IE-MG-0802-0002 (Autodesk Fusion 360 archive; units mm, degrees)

design "IS-MG-0802-0001" references "LED", "Ethernet Port", "SFP SLOT", "Digitus_DN-651107_LAN-Switch", "POWER"
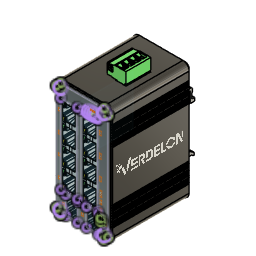
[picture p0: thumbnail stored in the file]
sketch "Sketch2" plane through (0, 0, 0) normal (0, 1, 0) x axis (1, 0, 0)
  line L1 (40, 0) -> (5, 0)
  line L2 (45, -90) -> (45, -5)
  line L3 (5, -95) -> (40, -95)
  line L4 (0, -5) -> (0, -90)
  arc A1 centre (5, -90) radius 5 clockwise from (5, -95) to (0, -90)
  arc A2 centre (40, -90) radius 5 clockwise from (45, -90) to (40, -95)
  arc A3 centre (40, -5) radius 5 clockwise from (40, 0) to (45, -5)
  arc A4 centre (5, -5) radius 5 clockwise from (0, -5) to (5, 0)
  point P1 (0, 0)
  point P2 (0, 0)
  point P4 (0, -95)
  point P3 (45, 0)
  horizontal L1
  vertical L2
  horizontal L3
  vertical L4
  coincident P1 P2
  coincident P4 L3
  coincident P4 L4
  tangent L3 A1
  tangent L4 A1
  tangent L2 A2
  tangent L3 A2
  equal A1 A2
  coincident P3 L1
  coincident P3 L2
  tangent L1 A3
  tangent L2 A3
  equal A1 A3
  coincident P2 L1
  coincident P2 L4
  tangent L1 A4
  tangent L4 A4
  dimension "d1" distance P2 P4 = 95
  dimension "d2" distance P2 P3 = 45
  dimension "d3" radius A1 = 5
  dimension "d6" radius A4 = 5
extrude "Extrude1" new body sketch "Sketch2" against normal blind 65
sketch "Sketch8" plane through (0, 0, 0) normal (0, 1, 0) x axis (-1, 0, 0)
  line L1 (-5, 0) -> (-40, 0)
  line L2 (0, 90) -> (0, 5)
  line L3 (-40, 95) -> (-5, 95)
  line L4 (-45, 5) -> (-45, 90)
  line L5 (-5, 1.5) -> (-40, 1.5)
  line L6 (-40, 0) -> (-5, 0)
  line L7 (-5, 95) -> (-40, 95)
  line L8 (0, 5) -> (0, 90)
  line L9 (-45, 5) -> (-45, 90)
  line L10 (-40, 1.5) -> (-5, 1.5)
  line L11 (-43.5, 5) -> (-43.5, 90)
  line L12 (-5, 93.5) -> (-40, 93.5)
  line L13 (-1.5, 5) -> (-1.5, 90)
  line L14 (0, 5) -> (0, 90)
  arc A1 centre (-40, 5) radius 5 clockwise from (-40, 0) to (-45, 5)
  arc A2 centre (-5, 5) radius 5 clockwise from (0, 5) to (-5, 0)
  arc A3 centre (-5, 90) radius 5 clockwise from (-5, 95) to (0, 90)
  arc A4 centre (-40, 90) radius 5 clockwise from (-45, 90) to (-40, 95)
  arc A5 centre (-40, 90) radius 4.6022 clockwise from (-43.6478, 87.194) to (-44.1163, 87.9418)
  arc A6 centre (-40, 5) radius 3.5 clockwise from (-40, 1.5) to (-43.5, 5)
  arc A7 centre (-5, 5) radius 3.5 clockwise from (-1.5, 5) to (-5, 1.5)
  arc A8 centre (-40, 90) radius 5 clockwise from (-45, 90) to (-40, 95)
  arc A9 centre (-5, 90) radius 5 clockwise from (-5, 95) to (0, 90)
  arc A10 centre (-5, 5) radius 5 clockwise from (0, 5) to (-5, 0)
  arc A11 centre (-40, 5) radius 5 clockwise from (-40, 0) to (-45, 5)
  arc A12 centre (-40, 5) radius 3.5 clockwise from (-40, 1.5) to (-43.5, 5)
  arc A13 centre (-40, 90) radius 3.5 clockwise from (-43.5, 90) to (-40, 93.5)
  arc A14 centre (-5, 90) radius 3.5 clockwise from (-5, 93.5) to (-1.5, 90)
  arc A15 centre (-5, 5) radius 3.5 clockwise from (-1.5, 5) to (-5, 1.5)
  horizontal L6
  horizontal L7
  vertical L8
  tangent L7 A8
  tangent L7 A9
  tangent L8 A9
  tangent L6 A10
  tangent L8 A10
  tangent L6 A11
  concentric A4 A5
  concentric A1 A6
  concentric A2 A7
  tangent A6 L5
  tangent L5 A7
  tangent A11 L9
  dimension "d14" radius A8 = 5
  dimension "d15" radius A9 = 5
  dimension "d16" radius A10 = 5
  dimension "d17" radius A11 = 5
  dimension "d168" = -1.5
  dimension "d169" distance L8 = 0
extrude "Extrude2" cut sketch "Sketch8" profile of A1 L1 A2 L2 A3 L3 A4 L4 L5 A6 A7 L6 L7 L8 A9 A10 L13 A12 L10 L12 L11 A15 A13 A14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 against normal blind 1.5
sketch "Sketch15" plane through (0, -65, 0) normal (0, -1, 0) x axis (1, 0, 0)
  line L1 (45, 90) -> (45, 5)
  line L2 (5, 95) -> (40, 95)
  line L3 (0, 5) -> (0, 90)
  line L4 (40, 0) -> (5, 0)
  line L5 (40, 1.5) -> (5, 1.5)
  line L6 (43.5, 90) -> (43.5, 5)
  line L7 (5, 93.5) -> (40, 93.5)
  line L8 (1.5, 5) -> (1.5, 90)
  line L9 (0, 5) -> (0, 90)
  line L10 (40, 0) -> (5, 0)
  line L11 (45, 90) -> (45, 5)
  line L12 (5, 95) -> (40, 95)
  arc A1 centre (40, 5) radius 5 clockwise from (45, 5) to (40, 0)
  arc A2 centre (40, 90) radius 5 clockwise from (40, 95) to (45, 90)
  arc A3 centre (5, 90) radius 5 clockwise from (0, 90) to (5, 95)
  arc A4 centre (5, 5) radius 5 clockwise from (5, 0) to (0, 5)
  arc A5 centre (40, 5) radius 3.5 clockwise from (43.5, 5) to (40, 1.5)
  arc A6 centre (40, 90) radius 3.5 clockwise from (40, 93.5) to (43.5, 90)
  arc A7 centre (5, 90) radius 3.5 clockwise from (1.5, 90) to (5, 93.5)
  arc A8 centre (5, 5) radius 3.5 clockwise from (5, 1.5) to (1.5, 5)
  arc A9 centre (5, 5) radius 5 clockwise from (5, 0) to (0, 5)
  arc A10 centre (40, 5) radius 5 clockwise from (45, 5) to (40, 0)
  arc A11 centre (40, 90) radius 5 clockwise from (40, 95) to (45, 90)
  arc A12 centre (5, 90) radius 5 clockwise from (0, 90) to (5, 95)
  dimension "d170" = -1.5
  dimension "d171" distance L3 = 0
  dimension "d172" = 0
extrude "Extrude3" cut sketch "Sketch15" against normal blind 1.5
sketch "Sketch17" plane through (0, -63.5, 0) normal (0, -1, 0) x axis (1, 0, 0)
  line L1 (40, 0) -> (5, 0)
  line L2 (45, 90) -> (45, 5)
  line L3 (5, 95) -> (40, 95)
  line L4 (0, 5) -> (0, 90)
  line L5 (-18.3053, 47.5) -> (0, 47.5)
  line L6 (0.5, 68.5) -> (0, 68.5)
  line L7 (0.5, 67.5) -> (0.5, 68.5)
  line L8 (0, 67.5) -> (0.5, 67.5)
  line L9 (0, 68.5) -> (0, 67.5)
  line L10 (0.5, 69.25) -> (0.5, 70.25)
  line L11 (0, 69.25) -> (0.5, 69.25)
  line L12 (0, 70.25) -> (0, 69.25)
  line L13 (0.5, 70.25) -> (0, 70.25)
  line L14 (0.5, 71) -> (0.5, 72)
  line L15 (0, 71) -> (0.5, 71)
  line L16 (0, 72) -> (0, 71)
  line L17 (0.5, 72) -> (0, 72)
  line L18 (0, 76) -> (0, 75)
  line L19 (0.5, 75) -> (0.5, 76)
  line L20 (0, 77.75) -> (0, 76.75)
  line L21 (0, 73.25) -> (0.5, 73.25)
  line L22 (0, 76.75) -> (0.5, 76.75)
  line L23 (0.5, 73.25) -> (0.5, 74.25)
  line L24 (0.5, 76) -> (0, 76)
  line L25 (0.5, 76.75) -> (0.5, 77.75)
  line L26 (0.5, 74.25) -> (0, 74.25)
  line L27 (0.5, 77.75) -> (0, 77.75)
  line L28 (0, 74.25) -> (0, 73.25)
  line L29 (0, 75) -> (0.5, 75)
  line L30 (0, 81.75) -> (0, 80.75)
  line L31 (0.5, 80.75) -> (0.5, 81.75)
  line L32 (0, 83.5) -> (0, 82.5)
  line L33 (0, 79) -> (0.5, 79)
  line L34 (0, 82.5) -> (0.5, 82.5)
  line L35 (0.5, 79) -> (0.5, 80)
  line L36 (0.5, 81.75) -> (0, 81.75)
  line L37 (0.5, 82.5) -> (0.5, 83.5)
  line L38 (0.5, 80) -> (0, 80)
  line L39 (0.5, 83.5) -> (0, 83.5)
  line L40 (0, 80) -> (0, 79)
  line L41 (0, 80.75) -> (0.5, 80.75)
  line L42 (0.5, 17.25) -> (0, 17.25)
  line L43 (0, 20.75) -> (0, 21.75)
  line L44 (0.5, 20) -> (0.5, 19)
  line L45 (0, 23) -> (0, 24)
  line L46 (0, 19) -> (0, 20)
  line L47 (0, 15) -> (0, 16)
  line L48 (0.5, 13.25) -> (0, 13.25)
  line L49 (0, 17.25) -> (0, 18.25)
  line L50 (0.5, 27.5) -> (0.5, 26.5)
  line L51 (0, 13.25) -> (0, 14.25)
  line L52 (0.5, 21.75) -> (0.5, 20.75)
  line L53 (0.5, 18.25) -> (0.5, 17.25)
  line L54 (0, 27.5) -> (0.5, 27.5)
  line L55 (0, 16) -> (0.5, 16)
  line L56 (0.5, 14.25) -> (0.5, 13.25)
  line L57 (0.5, 20.75) -> (0, 20.75)
  line L58 (0.5, 24.75) -> (0, 24.75)
  line L59 (0.5, 11.5) -> (0, 11.5)
  line L60 (0.5, 19) -> (0, 19)
  line L61 (0, 24) -> (0.5, 24)
  line L62 (0, 25.75) -> (0.5, 25.75)
  line L63 (0.5, 16) -> (0.5, 15)
  line L64 (0, 11.5) -> (0, 12.5)
  line L65 (0, 14.25) -> (0.5, 14.25)
  line L66 (0, 20) -> (0.5, 20)
  line L67 (0.5, 26.5) -> (0, 26.5)
  line L68 (0.5, 12.5) -> (0.5, 11.5)
  line L69 (0, 24.75) -> (0, 25.75)
  line L70 (0.5, 25.75) -> (0.5, 24.75)
  line L71 (0, 12.5) -> (0.5, 12.5)
  line L72 (0, 18.25) -> (0.5, 18.25)
  line L73 (0.5, 15) -> (0, 15)
  line L74 (0.5, 23) -> (0, 23)
  line L75 (0, 21.75) -> (0.5, 21.75)
  line L76 (0.5, 24) -> (0.5, 23)
  line L77 (0, 26.5) -> (0, 27.5)
  line L78 (22.5, 100) -> (22.5, 95)
  line L79 (45, 82.5) -> (44.5, 82.5)
  line L80 (45, 77.75) -> (45, 76.75)
  line L81 (44.5, 80) -> (45, 80)
  line L82 (45, 76.75) -> (44.5, 76.75)
  line L83 (45, 68.5) -> (45, 67.5)
  line L84 (45, 75) -> (44.5, 75)
  line L85 (44.5, 76) -> (45, 76)
  line L86 (44.5, 82.5) -> (44.5, 83.5)
  line L87 (45, 74.25) -> (45, 73.25)
  line L88 (44.5, 80.75) -> (44.5, 81.75)
  line L89 (44.5, 68.5) -> (45, 68.5)
  line L90 (45, 67.5) -> (44.5, 67.5)
  line L91 (45, 79) -> (44.5, 79)
  line L92 (45, 70.25) -> (45, 69.25)
  line L93 (44.5, 75) -> (44.5, 76)
  line L94 (45, 73.25) -> (44.5, 73.25)
  line L95 (44.5, 72) -> (45, 72)
  line L96 (45, 80) -> (45, 79)
  line L97 (44.5, 67.5) -> (44.5, 68.5)
  line L98 (44.5, 74.25) -> (45, 74.25)
  line L99 (44.5, 70.25) -> (45, 70.25)
  line L100 (45, 76) -> (45, 75)
  line L101 (44.5, 77.75) -> (45, 77.75)
  line L102 (45, 69.25) -> (44.5, 69.25)
  line L103 (44.5, 71) -> (44.5, 72)
  line L104 (44.5, 69.25) -> (44.5, 70.25)
  line L105 (44.5, 83.5) -> (45, 83.5)
  line L106 (45, 81.75) -> (45, 80.75)
  line L107 (44.5, 79) -> (44.5, 80)
  line L108 (44.5, 73.25) -> (44.5, 74.25)
  line L109 (44.5, 81.75) -> (45, 81.75)
  line L110 (45, 80.75) -> (44.5, 80.75)
  line L111 (45, 71) -> (44.5, 71)
  line L112 (44.5, 76.75) -> (44.5, 77.75)
  line L113 (45, 83.5) -> (45, 82.5)
  line L114 (45, 72) -> (45, 71)
  line L115 (44.5, 21.75) -> (44.5, 20.75)
  line L116 (44.5, 14.25) -> (44.5, 13.25)
  line L117 (45, 21.75) -> (44.5, 21.75)
  line L118 (44.5, 11.5) -> (45, 11.5)
  line L119 (45, 11.5) -> (45, 12.5)
  line L120 (44.5, 13.25) -> (45, 13.25)
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  point P15 (0, 47.5)
  point P17 (0, 68.5)
  point P78 (0, 26.5)
  point P18 (0.5, 68.5)
  point P88 (0.5, 26.5)
  point P19 (0.5, 67.5)
  point P60 (0.5, 27.5)
  point P20 (0, 67.5)
  point P81 (0, 27.5)
  point P21 (0.5, 70.25)
  point P87 (0.5, 24.75)
  point P22 (0.5, 69.25)
  point P82 (0.5, 25.75)
  point P23 (0, 69.25)
  point P79 (0, 25.75)
  point P24 (0, 70.25)
  point P85 (0, 24.75)
  point P25 (0.5, 72)
  point P71 (0.5, 23)
  point P26 (0.5, 71)
  point P67 (0.5, 24)
  point P27 (0, 71)
  point P69 (0, 24)
  point P28 (0, 72)
  point P65 (0, 23)
  point P29 (0, 75)
  point P63 (0, 20)
  point P30 (0, 76)
  point P56 (0, 19)
  point P31 (0.5, 74.25)
  point P55 (0.5, 20.75)
  point P32 (0, 73.25)
  point P59 (0, 21.75)
  point P33 (0.5, 73.25)
  point P54 (0.5, 21.75)
  point P34 (0, 74.25)
  point P53 (0, 20.75)
  point P35 (0.5, 76)
  point P58 (0.5, 19)
  point P36 (0.5, 75)
  point P57 (0.5, 20)
  point P37 (0, 76.75)
  point P62 (0, 18.25)
  point P38 (0, 77.75)
  point P75 (0, 17.25)
  point P39 (0.5, 77.75)
  point P73 (0.5, 17.25)
  point P40 (0.5, 76.75)
  point P84 (0.5, 18.25)
  point P41 (0, 80.75)
  point P70 (0, 14.25)
  point P42 (0, 81.75)
  point P64 (0, 13.25)
  point P43 (0.5, 80)
  point P61 (0.5, 15)
  point P44 (0, 79)
  point P66 (0, 16)
  point P45 (0.5, 79)
  point P76 (0.5, 16)
  point P46 (0, 80)
  point P68 (0, 15)
  point P47 (0.5, 81.75)
  point P72 (0.5, 13.25)
  point P48 (0.5, 80.75)
  point P74 (0.5, 14.25)
  point P49 (0, 82.5)
  point P77 (0, 12.5)
  point P50 (0, 83.5)
  point P80 (0, 11.5)
  point P51 (0.5, 83.5)
  point P83 (0.5, 11.5)
  point P52 (0.5, 82.5)
  point P86 (0.5, 12.5)
  point P89 (22.5, 95)
  point P2 (5, 5)
  point P155 (40, 5)
  point P3 (5, 90)
  point P113 (40, 90)
  point P13 (0, 90)
  point P108 (45, 90)
  point P14 (0, 5)
  point P153 (45, 5)
  point P92 (45, 68.5)
  point P114 (44.5, 68.5)
  point P168 (44.5, 67.5)
  point P167 (45, 67.5)
  point P104 (44.5, 70.25)
  point P103 (44.5, 69.25)
  point P101 (45, 69.25)
  point P98 (45, 70.25)
  point P111 (44.5, 72)
  point P100 (44.5, 71)
  point P110 (45, 71)
  point P102 (45, 72)
  point P107 (45, 75)
  point P109 (45, 76)
  point P105 (44.5, 74.25)
  point P106 (45, 73.25)
  point P91 (44.5, 73.25)
  point P99 (45, 74.25)
  point P117 (44.5, 76)
  point P116 (44.5, 75)
  point P115 (45, 76.75)
  point P119 (45, 77.75)
  point P120 (44.5, 77.75)
  point P121 (44.5, 76.75)
  point P118 (45, 80.75)
  point P125 (45, 81.75)
  point P123 (44.5, 80)
  point P122 (45, 79)
  point P126 (44.5, 79)
  point P97 (45, 80)
  point P124 (44.5, 81.75)
  point P96 (44.5, 80.75)
  point P95 (45, 82.5)
  point P93 (45, 83.5)
  point P94 (44.5, 83.5)
  point P127 (44.5, 82.5)
  point P129 (45, 20.75)
  point P135 (44.5, 21.75)
  point P144 (44.5, 20.75)
  point P149 (45, 19)
  point P146 (44.5, 20)
  point P160 (44.5, 19)
  point P164 (45, 21.75)
  point P165 (44.5, 27.5)
  point P162 (44.5, 15)
  point P161 (45, 18.25)
  point P157 (45, 20)
  point P163 (45, 13.25)
  point P147 (45, 23)
  point P166 (45, 16)
  point P150 (44.5, 24)
  point P158 (45, 15)
  point P152 (45, 24)
  point P159 (45, 14.25)
  point P137 (44.5, 23)
  point P148 (44.5, 13.25)
  point P143 (44.5, 17.25)
  point P156 (44.5, 14.25)
  point P139 (45, 17.25)
  point P154 (44.5, 16)
  point P151 (45, 12.5)
  point P134 (45, 26.5)
  point P133 (45, 25.75)
  point P138 (45, 11.5)
  point P132 (45, 27.5)
  point P141 (44.5, 25.75)
  point P145 (44.5, 11.5)
  point P131 (44.5, 18.25)
  point P140 (45, 24.75)
  point P136 (44.5, 12.5)
  point P128 (44.5, 24.75)
  point P130 (44.5, 26.5)
  midpoint L4 P15
  perpendicular L4 L5
  horizontal L6
  vertical L7
  horizontal L8
  vertical L9
  coincident L4 P17
  symmetric L5 P17 P78
  symmetric L5 P18 P88
  symmetric L5 P19 P60
  symmetric L5 P20 P81
  symmetric L5 P21 P87
  symmetric L5 P22 P82
  symmetric L5 P23 P79
  symmetric L5 P24 P85
  symmetric L5 P25 P71
  symmetric L5 P26 P67
  symmetric L5 P27 P69
  symmetric L5 P28 P65
  symmetric L5 P29 P63
  symmetric L5 P30 P56
  symmetric L5 P31 P55
  symmetric L5 P32 P59
  symmetric L5 P33 P54
  symmetric L5 P34 P53
  symmetric L5 P35 P58
  symmetric L5 P36 P57
  symmetric L5 P37 P62
  symmetric L5 P38 P75
  symmetric L5 P39 P73
  symmetric L5 P40 P84
  symmetric L5 P41 P70
  symmetric L5 P42 P64
  symmetric L5 P43 P61
  symmetric L5 P44 P66
  symmetric L5 P45 P76
  symmetric L5 P46 P68
  symmetric L5 P47 P72
  symmetric L5 P48 P74
  symmetric L5 P49 P77
  symmetric L5 P50 P80
  symmetric L5 P51 P83
  symmetric L5 P52 P86
  midpoint L3 P89
  perpendicular L3 L78
  symmetric P2 L78 P155
  symmetric P3 L78 P113
  symmetric P13 L78 P108
  symmetric P14 L78 P153
  symmetric P17 L78 P92
  symmetric P18 L78 P114
  symmetric P19 L78 P168
  symmetric P20 L78 P167
  symmetric P21 L78 P104
  symmetric P22 L78 P103
  symmetric P23 L78 P101
  symmetric P24 L78 P98
  symmetric P25 L78 P111
  symmetric P26 L78 P100
  symmetric P27 L78 P110
  symmetric P28 L78 P102
  symmetric P29 L78 P107
  symmetric P30 L78 P109
  symmetric P31 L78 P105
  symmetric P32 L78 P106
  symmetric P33 L78 P91
  symmetric P34 L78 P99
  symmetric P35 L78 P117
  symmetric P36 L78 P116
  symmetric P37 L78 P115
  symmetric P38 L78 P119
  symmetric P39 L78 P120
  symmetric P40 L78 P121
  symmetric P41 L78 P118
  symmetric P42 L78 P125
  symmetric P43 L78 P123
  symmetric P44 L78 P122
  symmetric P45 L78 P126
  symmetric P46 L78 P97
  symmetric P47 L78 P124
  symmetric P48 L78 P96
  symmetric P49 L78 P95
  symmetric P50 L78 P93
  symmetric P51 L78 P94
  symmetric P52 L78 P127
  symmetric P53 L78 P129
  symmetric P54 L78 P135
  symmetric P55 L78 P144
  symmetric P56 L78 P149
  symmetric P57 L78 P146
  symmetric P58 L78 P160
  symmetric P59 L78 P164
  symmetric P60 L78 P165
  symmetric P61 L78 P162
  symmetric P62 L78 P161
  symmetric P63 L78 P157
  symmetric P64 L78 P163
  symmetric P65 L78 P147
  symmetric P66 L78 P166
  symmetric P67 L78 P150
  symmetric P68 L78 P158
  symmetric P69 L78 P152
  symmetric P70 L78 P159
  symmetric P71 L78 P137
  symmetric P72 L78 P148
  symmetric P73 L78 P143
  symmetric P74 L78 P156
  symmetric P75 L78 P139
  symmetric P76 L78 P154
  symmetric P77 L78 P151
  symmetric P78 L78 P134
  symmetric P79 L78 P133
  symmetric P80 L78 P138
  symmetric P81 L78 P132
  symmetric P82 L78 P141
  symmetric P83 L78 P145
  symmetric P84 L78 P131
  symmetric P85 L78 P140
  symmetric P86 L78 P136
  symmetric P87 L78 P128
  symmetric P88 L78 P130
  dimension "d43" distance P17 P18 = 0.5
  dimension "d44" distance P17 P20 = 1
  dimension "d45" distance L5 P19 = 20
  dimension "d48" R-Pattern1-uDistance = 0
  dimension "d49" R-Pattern1-vDistance = 3.5
  dimension "d52" R-Pattern2-uDistance = 0
  dimension "d53" R-Pattern2-vDistance = 11.5
extrude "Extrude6" cut sketch "Sketch17" against normal blind 130
fillet "Fillet3" radius 0.25 0.25
fillet "Fillet4" radius 0.25
delete_face "DeleteFace1"
fillet "Fillet6" radius 0.25
sketch "Sketch19" plane through (0, -65, 0) normal (0, -1, 0) x axis (1, 0, 0)
  line L1 (24, 45) -> (24, 88.25)
  line L2 (24, 45) -> (1.75, 45)
  line L3 (35.07, 83) -> (21.91, 83)
  line L4 (35.07, 19.2) -> (35.07, 83)
  line L5 (21.91, 19.2) -> (35.07, 19.2)
  line L6 (21.91, 83) -> (21.91, 19.2)
  line L7 (18.41, 83) -> (5.25, 83)
  line L8 (18.41, 19.2) -> (18.41, 83)
  line L9 (5.25, 19.2) -> (18.41, 19.2)
  line L10 (5.25, 83) -> (5.25, 19.2)
  line L11 (25.87, 17.7) -> (35.57, 17.7)
  line L12 (25.87, 3.2) -> (25.87, 17.7)
  line L13 (35.57, 3.2) -> (25.87, 3.2)
  line L14 (35.57, 17.7) -> (35.57, 3.2)
  line L15 (9.21, 17.7) -> (18.91, 17.7)
  line L16 (9.21, 3.2) -> (9.21, 17.7)
  line L17 (18.91, 3.2) -> (9.21, 3.2)
  line L18 (18.91, 17.7) -> (18.91, 3.2)
  line L19 (38.57, 15.2) -> (37.07, 15.2)
  line L20 (38.57, 12.7) -> (38.57, 15.2)
  line L21 (37.07, 12.7) -> (38.57, 12.7)
  line L22 (37.07, 15.2) -> (37.07, 12.7)
  line L23 (40, 1.75) -> (5, 1.75)
  line L24 (43.25, 90) -> (43.25, 5)
  line L25 (5, 93.25) -> (40, 93.25)
  line L26 (1.75, 5) -> (1.75, 90)
  circle C1 centre (33.57, 85) radius 0.75
  circle C2 centre (31.57, 85) radius 0.75
  circle C3 centre (29.57, 85) radius 0.75
  circle C4 centre (27.57, 85) radius 0.75
  arc A1 centre (40, 5) radius 3.25 clockwise from (43.25, 5) to (40, 1.75)
  arc A2 centre (40, 90) radius 3.25 clockwise from (40, 93.25) to (43.25, 90)
  arc A3 centre (5, 90) radius 3.25 clockwise from (1.75, 90) to (5, 93.25)
  arc A4 centre (5, 5) radius 3.25 clockwise from (5, 1.75) to (1.75, 5)
  point P5 (21.91, 83)
  point P6 (35.07, 83)
  point P7 (35.07, 19.2)
  point P9 (5.25, 83)
  point P10 (18.41, 83)
  point P12 (5.25, 19.2)
  point P13 (35.57, 17.7)
  point P16 (35.57, 3.2)
  point P14 (25.87, 17.7)
  point P17 (18.91, 17.7)
  point P18 (9.21, 17.7)
  point P19 (9.21, 3.2)
  point P3 (1.75, 45)
  point P21 (33.57, 85)
  point P26 (38.57, 15.2)
  point P27 (38.57, 12.7)
  point P25 (37.07, 15.2)
  horizontal L3
  vertical L4
  horizontal L5
  vertical L6
  horizontal L7
  vertical L8
  horizontal L9
  vertical L10
  horizontal L11
  vertical L12
  horizontal L13
  vertical L14
  horizontal L15
  vertical L16
  horizontal L17
  vertical L18
  collinear L3 L7
  collinear L11 L15
  horizontal L19
  vertical L20
  horizontal L21
  vertical L22
  dimension "d68" distance P5 P6 = 13.16
  dimension "d69" distance P6 P7 = 63.8
  dimension "d70" distance P9 P10 = 13.16
  dimension "d71" distance P9 P12 = 63.8
  dimension "d72" distance P13 P16 = 14.5
  dimension "d73" distance P13 P14 = 9.7
  dimension "d74" distance P17 P18 = 9.7
  dimension "d75" distance P18 P19 = 14.5
  dimension "d76" distance P3 L10 = 3.5
  dimension "d77" distance L6 L8 = 3.5
  dimension "d78" distance L2 L7 = 38
  dimension "d79" distance L5 L11 = 1.5
  dimension "d80" distance L4 L14 = 0.5
  dimension "d81" distance L8 L18 = 0.5
  dimension "d95" diameter C1 = 1.5
  dimension "d100" distance L3 P21 = 2
  dimension "d101" distance L4 P21 = 1.5
  dimension "d109" distance P26 P27 = 2.5
  dimension "d110" distance P25 P26 = 1.5
  dimension "d111" distance L11 L19 = 2.5
  dimension "d112" distance L14 L22 = 1.5
  dimension "d98" R-Pattern1-uDistance = -6
  dimension "d99" R-Pattern1-vDistance = 0
extrude "Extrude8" cut sketch "Sketch19" profile of L1 L2 L3 L4 L5 L6 L7 L8 L9 L10 L11 L12 L13 L14 L15 L16 L17 L18 C1 C2 C3 C4 L19 L20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 against normal blind 25
sketch "Sketch20" plane through (0, 0, 95) normal (0, 0, 1) x axis (-1, 0, 0)
  line L1 (-5, 1.75) -> (-40, 1.75)
  line L2 (-5, 63.25) -> (-5, 1.75)
  line L3 (-40, 63.25) -> (-5, 63.25)
  line L4 (-40, 1.75) -> (-40, 63.25)
  line L5 (-22.5, 32.5) -> (-22.5, 1.75)
  line L6 (-22.5, 32.5) -> (-40, 32.5)
  line L7 (-34.5, 22.5) -> (-26.83, 22.5)
  line L8 (-34.5, 42.5) -> (-34.5, 22.5)
  line L9 (-26.83, 42.5) -> (-34.5, 42.5)
  line L10 (-26.83, 22.5) -> (-26.83, 42.5)
  point P6 (-22.5, 1.75)
  point P7 (-40, 32.5)
  point P9 (-26.83, 22.5)
  point P10 (-34.5, 22.5)
  point P12 (-26.83, 42.5)
  midpoint L1 P6
  perpendicular L1 L5
  midpoint L4 P7
  perpendicular L4 L6
  horizontal L7
  vertical L8
  horizontal L9
  vertical L10
  symmetric L6 L7 L9
  dimension "d88" distance P9 P10 = 7.67
  dimension "d89" distance P9 P12 = 20
  dimension "d90" distance L5 L8 = 12
extrude "Extrude9" cut sketch "Sketch20" profile of L6 L7 L8 L9 L10 against normal blind 5
shell "Shell6" innerThickness 1
sketch "Sketch22" plane through (0, -65, 0) normal (0, -1, 0) x axis (1, 0, 0)
  line L1 (35.07, 19.2) -> (35.07, 83)
  line L2 (21.91, 19.2) -> (35.07, 19.2)
  line L3 (21.91, 83) -> (21.91, 19.2)
  line L4 (35.07, 83) -> (21.91, 83)
  line L5 (18.91, 17.7) -> (9.21, 17.7)
  line L6 (18.91, 3.2) -> (18.91, 17.7)
  line L7 (9.21, 3.2) -> (18.91, 3.2)
  line L8 (9.21, 17.7) -> (9.21, 3.2)
  line L9 (18.41, 19.2) -> (18.41, 83)
  line L10 (5.25, 19.2) -> (18.41, 19.2)
  line L11 (5.25, 83) -> (5.25, 19.2)
  line L12 (18.41, 83) -> (5.25, 83)
  line L13 (35.57, 17.7) -> (25.87, 17.7)
  line L14 (35.57, 3.2) -> (35.57, 17.7)
  line L15 (25.87, 3.2) -> (35.57, 3.2)
  line L16 (25.87, 17.7) -> (25.87, 3.2)
  curve K1
  curve K2
  curve K3
  curve K4
  line L17 (38.57, 12.7) -> (38.57, 15.2)
  line L18 (37.07, 12.7) -> (38.57, 12.7)
  line L19 (37.07, 15.2) -> (37.07, 12.7)
  line L20 (38.57, 15.2) -> (37.07, 15.2)
  line L21 (40, 1.75) -> (5, 1.75)
  line L22 (43.25, 90) -> (43.25, 5)
  line L23 (5, 93.25) -> (40, 93.25)
  line L24 (1.75, 5) -> (1.75, 90)
  line L25 (18.91, 17.7) -> (9.21, 17.7)
  line L26 (18.91, 3.2) -> (18.91, 17.7)
  line L27 (9.21, 3.2) -> (18.91, 3.2)
  line L28 (9.21, 17.7) -> (9.21, 3.2)
  line L29 (35.07, 19.2) -> (35.07, 83)
  line L30 (21.91, 19.2) -> (35.07, 19.2)
  line L31 (21.91, 83) -> (21.91, 19.2)
  line L32 (35.07, 83) -> (21.91, 83)
  line L33 (35.57, 17.7) -> (25.87, 17.7)
  line L34 (35.57, 3.2) -> (35.57, 17.7)
  line L35 (25.87, 3.2) -> (35.57, 3.2)
  line L36 (25.87, 17.7) -> (25.87, 3.2)
  line L37 (18.41, 19.2) -> (18.41, 83)
  line L38 (5.25, 19.2) -> (18.41, 19.2)
  line L39 (5.25, 83) -> (5.25, 19.2)
  line L40 (18.41, 83) -> (5.25, 83)
  line L41 (38.57, 12.7) -> (38.57, 15.2)
  line L42 (37.07, 12.7) -> (38.57, 12.7)
  line L43 (37.07, 15.2) -> (37.07, 12.7)
  line L44 (38.57, 15.2) -> (37.07, 15.2)
  line L45 (40, 1.75) -> (5, 1.75)
  line L46 (43.25, 90) -> (43.25, 5)
  line L47 (5, 93.25) -> (40, 93.25)
  line L48 (1.75, 5) -> (1.75, 90)
  circle C1 centre (31.57, 85) radius 0.75
  circle C2 centre (29.57, 85) radius 0.75
  circle C3 centre (33.57, 85) radius 0.75
  circle C4 centre (27.57, 85) radius 0.75
  arc A1 centre (40, 5) radius 3.25 clockwise from (43.25, 5) to (40, 1.75)
  arc A2 centre (40, 90) radius 3.25 clockwise from (40, 93.25) to (43.25, 90)
  arc A3 centre (5, 90) radius 3.25 clockwise from (1.75, 90) to (5, 93.25)
  arc A4 centre (5, 5) radius 3.25 clockwise from (5, 1.75) to (1.75, 5)
  circle C5 centre (29.57, 85) radius 0.75
  circle C6 centre (31.57, 85) radius 0.75
  circle C7 centre (27.57, 85) radius 0.75
  circle C8 centre (33.57, 85) radius 0.75
  arc A5 centre (40, 5) radius 3.25 clockwise from (43.25, 5) to (40, 1.75)
  arc A6 centre (40, 90) radius 3.25 clockwise from (40, 93.25) to (43.25, 90)
  arc A7 centre (5, 90) radius 3.25 clockwise from (1.75, 90) to (5, 93.25)
  arc A8 centre (5, 5) radius 3.25 clockwise from (5, 1.75) to (1.75, 5)
  dimension "d105" Text1-Height = 0.7
sketch "Sketch23" plane through (0, -65, 0) normal (0, -1, 0) x axis (1, 0, 0)
  dimension "d106" = 0.8
sketch "Sketch24" plane through (0, -65, 0) normal (0, -1, 0) x axis (1, 0, 0)
  dimension "d107" = 0.8
sketch "Sketch25" plane through (0, -65, 0) normal (0, -1, 0) x axis (1, 0, 0)
sketch "Sketch26" plane through (0, -65, 0) normal (0, -1, 0) x axis (1, 0, 0)
  dimension "d114" = 1.2
  dimension "d115" = 1.2
  dimension "d116" = 1.2
  dimension "d117" = 1.2
  dimension "d118" = 1.2
  dimension "d119" = 1.2
  dimension "d120" = 1.2
  dimension "d121" = 1.2
  dimension "d122" = 1.2
  dimension "d123" = 1.2
  dimension "d124" = 1.2
  dimension "d125" = 1.2
  dimension "d126" = 1.2
sketch "Sketch36" plane through (0, -65, 0) normal (0, -1, 0) x axis (1, 0, 0)
  circle C1 centre (5, 90) radius 0.84
  circle C2 centre (40, 90) radius 0.84
  circle C3 centre (5, 5) radius 0.84
  circle C4 centre (40, 5) radius 0.84
  dimension "d145" diameter C1 = 1.68
  dimension "d177" R-Pattern1-uDistance = 35
  dimension "d178" R-Pattern1-vDistance = 0
  dimension "d181" R-Pattern2-uDistance = 0
  dimension "d182" R-Pattern2-vDistance = -85
sketch "Sketch27" plane through (0, -65, 0) normal (0, -1, 0) x axis (1, 0, 0)
sketch "Sketch28" plane through (0, -65, 0) normal (0, -1, 0) x axis (1, 0, 0)
component_insert "Component Insert3"
rectangular_pattern "00000000-0000-0000-0000-000000000000" uSpaceDistance -16.66 vSpaceDistance 0
fillet "Fillet7" radius 0.8 0.8 0.8
component_insert "Component Insert4"
sketch "Sketch33" plane through (0, -65, 0) normal (0, -1, 0) x axis (1, 0, 0)
  line L1 (18.11, 17.7) -> (10.01, 17.7)
  line L2 (18.91, 4) -> (18.91, 16.9)
  line L3 (10.01, 3.2) -> (18.11, 3.2)
  line L4 (9.21, 16.9) -> (9.21, 4)
  line L5 (35.07, 19.2) -> (35.07, 83)
  line L6 (21.91, 19.2) -> (35.07, 19.2)
  line L7 (21.91, 83) -> (21.91, 19.2)
  line L8 (35.07, 83) -> (21.91, 83)
  line L9 (34.77, 17.7) -> (26.67, 17.7)
  line L10 (35.57, 4) -> (35.57, 16.9)
  line L11 (26.67, 3.2) -> (34.77, 3.2)
  line L12 (25.87, 16.9) -> (25.87, 4)
  line L13 (18.41, 19.2) -> (18.41, 83)
  line L14 (5.25, 19.2) -> (18.41, 19.2)
  line L15 (5.25, 83) -> (5.25, 19.2)
  line L16 (18.41, 83) -> (5.25, 83)
  line L17 (38.57, 12.7) -> (38.57, 15.2)
  line L18 (37.07, 12.7) -> (38.57, 12.7)
  line L19 (37.07, 15.2) -> (37.07, 12.7)
  line L20 (38.57, 15.2) -> (37.07, 15.2)
  circle C1 centre (29.57, 85) radius 0.75
  arc A1 centre (18.11, 16.9) radius 0.8 clockwise from (18.11, 17.7) to (18.91, 16.9)
  arc A2 centre (18.11, 4) radius 0.8 clockwise from (18.91, 4) to (18.11, 3.2)
  arc A3 centre (10.01, 4) radius 0.8 clockwise from (10.01, 3.2) to (9.21, 4)
  arc A4 centre (10.01, 16.9) radius 0.8 clockwise from (9.21, 16.9) to (10.01, 17.7)
  circle C2 centre (31.57, 85) radius 0.75
  circle C3 centre (27.57, 85) radius 0.75
  arc A5 centre (34.77, 16.9) radius 0.8 clockwise from (34.77, 17.7) to (35.57, 16.9)
  arc A6 centre (34.77, 4) radius 0.8 clockwise from (35.57, 4) to (34.77, 3.2)
  arc A7 centre (26.67, 4) radius 0.8 clockwise from (26.67, 3.2) to (25.87, 4)
  arc A8 centre (26.67, 16.9) radius 0.8 clockwise from (25.87, 16.9) to (26.67, 17.7)
  circle C4 centre (33.57, 85) radius 0.75
position "Position1"
rectangular_pattern "00000000-0000-0000-0000-000000000000" uSpaceDistance -6 vSpaceDistance 0
component_insert "Component Insert8"
sketch "Sketch40" plane through (0, 0, 0) normal (-1, 0, 0) x axis (0, -1, 0)
  line L1 (1.75, 27.5) -> (1.75, 67.5)
  line L2 (63.25, 27.5) -> (1.75, 27.5)
  line L3 (63.25, 67.5) -> (63.25, 27.5)
  line L4 (1.75, 67.5) -> (63.25, 67.5)
decal "Decal3"
decal "Decal4"
component_insert "Component Insert9"
position "Position4"
rectangular_pattern "00000000-0000-0000-0000-000000000000" uSpaceDistance -16.68 vSpaceDistance 0
component_insert "Component Insert12"

design "Ethernet Port"
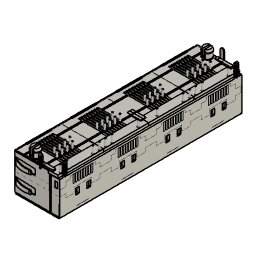
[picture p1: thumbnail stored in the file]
description: STEP AP214
part number: Ethernet Port

design "POWER"
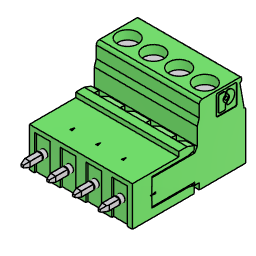
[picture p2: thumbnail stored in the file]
description: STEP AP214
part number: POWER

design "Digitus_DN-651107_LAN-Switch"
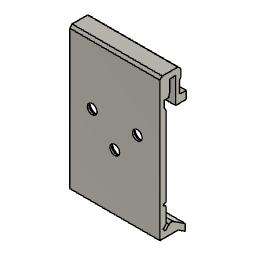
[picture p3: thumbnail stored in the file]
description: STEP AP214
part number: Digitus_DN-651107_LAN-Switch

design "LED"
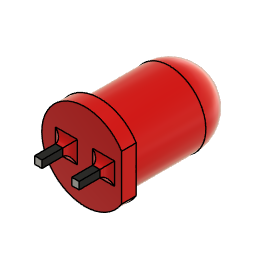
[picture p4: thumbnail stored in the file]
description: STEP AP214
part number: LED

design "SFP SLOT"
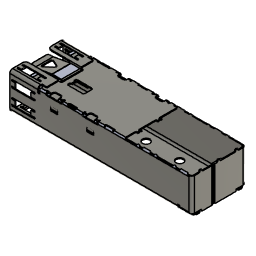
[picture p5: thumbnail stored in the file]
description: STEP AP214
part number: SFP SLOT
